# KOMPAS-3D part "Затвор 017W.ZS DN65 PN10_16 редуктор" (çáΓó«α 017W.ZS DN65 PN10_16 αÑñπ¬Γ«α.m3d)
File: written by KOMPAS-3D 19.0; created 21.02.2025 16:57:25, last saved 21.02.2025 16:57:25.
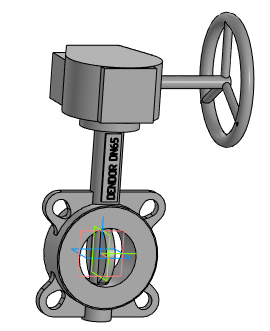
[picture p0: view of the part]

Document properties: Автор: Евгений; Полное имя файла: Затвор 017W.ZS DN65 PN10_16 редуктор.a3d

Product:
- Part/product: Затвор 017W.ZS DN65 PN10_16 редуктор
    Масса: 10.0813

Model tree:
1. Операция без истории:1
